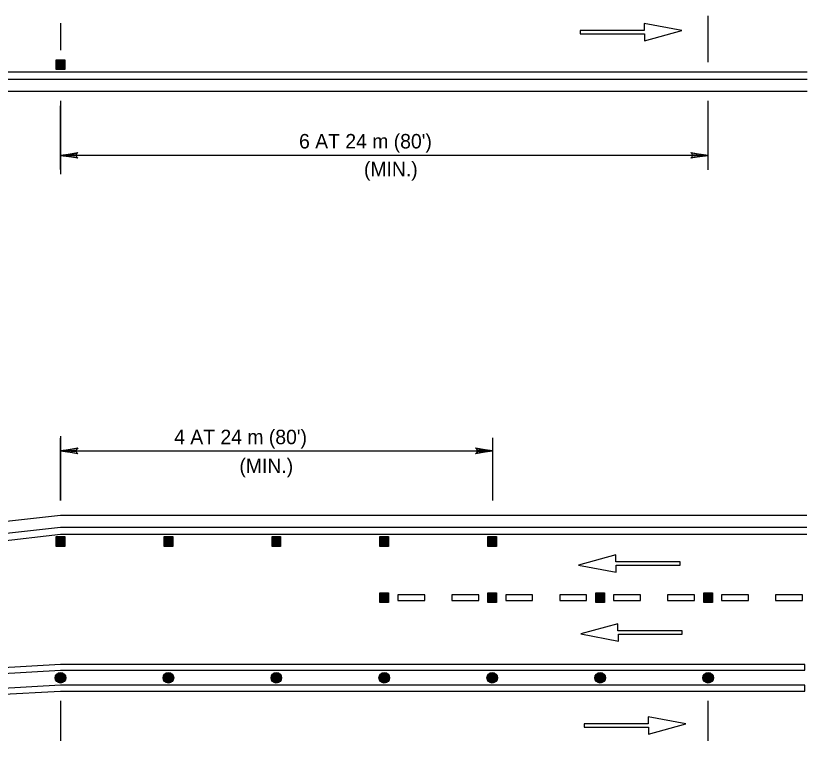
# Model space of a CAD drawing. Extents: x 639362 to 641108, y 298458 to 299646.
# Drawn here: x 639788.7 to 639952.7, y 298599.3 to 298751.3 of the extents above; entities that cross this region are included whole.
import ezdxf

# ---------------------------------------------------------------- set-up
doc = ezdxf.new("R2010")
doc.units = 0
doc.layers.add('2', color=7, linetype='Continuous')
doc.layers.add('3', color=7, linetype='Continuous')

# ---------------------------------------------------------------- blocks, each defined once
blk = doc.blocks.new('RARROW')
at = {"layer": '3'}
blk.add_lwpolyline([(-2.2695, 0.285), (-2.184875, 0.12075), (0, 0), (-2.2695, 0.285), (-2.38575, 0.384625), (0, 0), (-2.183125, -0.108), (-2.262875, -0.2705), (0, 0), (-2.38575, -0.379125), (-2.262875, -0.2705)], dxfattribs=at)

msp = doc.modelspace()

# ---------------------------------------------------------------- linework, layer by layer
at = {"layer": '2'}
for p, q in [((639932.2, 298741.66), (639932.2, 298751.3)), ((639798, 298749.76), (639798, 298744.18)), ((639926.74, 298748.22), (639918.93, 298749.7)), ((639918.93, 298749.7), (639918.93, 298748.25)), ((639918.93, 298748.25), (639905.69, 298748.25)), ((639905.69, 298748.25), (639905.69, 298747.55)), ((639905.69, 298747.55), (639919.02, 298747.55)), ((639919.02, 298746.1), (639926.74, 298748.22)), ((639919.02, 298747.55), (639919.02, 298746.1)), ((639797.11, 298740.14), (639797.11, 298742.18)), ((639797.11, 298742.18), (639798.88, 298742.18)), ((639797.28, 298740.32), (639797.28, 298742)), ((639797.28, 298742), (639798.7, 298742)), ((639797.46, 298740.5), (639797.46, 298741.83)), ((639797.46, 298741.83), (639798.53, 298741.83)), ((639797.64, 298740.67), (639797.64, 298741.65)), ((639797.64, 298741.65), (639798.35, 298741.65)), ((639797.82, 298740.85), (639797.82, 298741.47)), ((639797.82, 298741.47), (639798.17, 298741.47)), ((639798, 298741.03), (639798, 298741.29)), ((639798.17, 298741.47), (639798.17, 298740.85)), ((639798.35, 298741.65), (639798.35, 298740.67)), ((639798.53, 298741.83), (639798.53, 298740.5)), ((639798.7, 298742), (639798.7, 298740.32)), ((639798.88, 298742.18), (639798.88, 298740.14)), ((639431.35, 298739.66), (639952.74, 298739.66)), ((639798.88, 298740.14), (639797.11, 298740.14)), ((639798.7, 298740.32), (639797.28, 298740.32)), ((639798.53, 298740.5), (639797.46, 298740.5)), ((639798.35, 298740.67), (639797.64, 298740.67)), ((639798.17, 298740.85), (639797.82, 298740.85)), ((639431.35, 298738.16), (639952.74, 298738.16)), ((639431.35, 298735.66), (639952.74, 298735.66)), ((639798, 298733.66), (639798, 298718.46)), ((639932.2, 298719.36), (639932.2, 298733.66)), ((639798, 298719.43), (639798, 298732.66)), ((639932.2, 298722.36), (639798, 298722.36)), ((639797.99, 298664.16), (639797.99, 298650.81)), ((639798, 298650.81), (639798, 298663.74)), ((639887.61, 298650.81), (639887.61, 298663.83)), ((639798.01, 298661.11), (639887.61, 298661.11)), ((639585.9, 298624.2), (639797.99, 298647.81)), ((639797.99, 298647.81), (639951.12, 298647.81)), ((639797.99, 298647.81), (639952.64, 298647.81)), ((639585.9, 298621.7), (639797.99, 298645.31)), ((639797.99, 298645.31), (639951.12, 298645.31)), ((639797.99, 298645.31), (639952.64, 298645.31)), ((639585.9, 298620.2), (639797.99, 298643.81)), ((639797.11, 298641.29), (639797.11, 298643.33)), ((639797.11, 298643.33), (639798.88, 298643.33)), ((639797.28, 298641.47), (639797.28, 298643.16)), ((639797.28, 298643.16), (639798.7, 298643.16)), ((639797.46, 298641.65), (639797.46, 298642.98)), ((639797.46, 298642.98), (639798.53, 298642.98)), ((639797.64, 298641.83), (639797.64, 298642.8)), ((639797.64, 298642.8), (639798.35, 298642.8)), ((639797.82, 298642), (639797.82, 298642.62)), ((639797.82, 298642.62), (639798.17, 298642.62)), ((639797.99, 298643.81), (639951.12, 298643.81)), ((639797.99, 298643.81), (639952.64, 298643.81)), ((639798.17, 298642.62), (639798.17, 298642)), ((639798.35, 298642.8), (639798.35, 298641.83)), ((639798.53, 298642.98), (639798.53, 298641.65)), ((639798.7, 298643.16), (639798.7, 298641.47)), ((639798.88, 298643.33), (639798.88, 298641.29)), ((639819.47, 298641.29), (639819.47, 298643.33)), ((639819.47, 298643.33), (639821.25, 298643.33)), ((639819.65, 298641.47), (639819.65, 298643.16)), ((639819.65, 298643.16), (639821.07, 298643.16)), ((639819.83, 298641.65), (639819.83, 298642.98)), ((639819.83, 298642.98), (639820.89, 298642.98)), ((639820.01, 298641.83), (639820.01, 298642.8)), ((639820.01, 298642.8), (639820.72, 298642.8)), ((639820.18, 298642), (639820.18, 298642.62)), ((639820.18, 298642.62), (639820.54, 298642.62)), ((639820.54, 298642.62), (639820.54, 298642)), ((639820.72, 298642.8), (639820.72, 298641.83)), ((639820.89, 298642.98), (639820.89, 298641.65)), ((639821.07, 298643.16), (639821.07, 298641.47)), ((639821.25, 298643.33), (639821.25, 298641.29)), ((639841.84, 298641.29), (639841.84, 298643.33)), ((639841.84, 298643.33), (639843.62, 298643.33)), ((639842.02, 298641.47), (639842.02, 298643.16)), ((639842.02, 298643.16), (639843.44, 298643.16)), ((639842.2, 298641.65), (639842.2, 298642.98)), ((639842.2, 298642.98), (639843.26, 298642.98)), ((639842.37, 298641.83), (639842.37, 298642.8)), ((639842.37, 298642.8), (639843.08, 298642.8)), ((639842.55, 298642), (639842.55, 298642.62)), ((639842.55, 298642.62), (639842.91, 298642.62)), ((639842.91, 298642.62), (639842.91, 298642)), ((639843.08, 298642.8), (639843.08, 298641.83)), ((639843.26, 298642.98), (639843.26, 298641.65)), ((639843.44, 298643.16), (639843.44, 298641.47)), ((639843.62, 298643.33), (639843.62, 298641.29)), ((639864.21, 298641.29), (639864.21, 298643.33)), ((639864.21, 298643.33), (639865.98, 298643.33)), ((639864.39, 298641.47), (639864.39, 298643.16)), ((639864.39, 298643.16), (639865.81, 298643.16)), ((639864.56, 298641.65), (639864.56, 298642.98)), ((639864.56, 298642.98), (639865.63, 298642.98)), ((639864.74, 298641.83), (639864.74, 298642.8)), ((639864.74, 298642.8), (639865.45, 298642.8)), ((639864.92, 298642), (639864.92, 298642.62)), ((639864.92, 298642.62), (639865.27, 298642.62)), ((639865.27, 298642.62), (639865.27, 298642)), ((639865.45, 298642.8), (639865.45, 298641.83)), ((639865.63, 298642.98), (639865.63, 298641.65)), ((639865.81, 298643.16), (639865.81, 298641.47)), ((639865.98, 298643.33), (639865.98, 298641.29)), ((639886.58, 298641.29), (639886.58, 298643.33)), ((639886.58, 298643.33), (639888.35, 298643.33)), ((639886.75, 298641.47), (639886.75, 298643.16)), ((639886.75, 298643.16), (639888.17, 298643.16)), ((639886.93, 298641.65), (639886.93, 298642.98)), ((639886.93, 298642.98), (639888, 298642.98)), ((639887.11, 298641.83), (639887.11, 298642.8)), ((639887.11, 298642.8), (639887.82, 298642.8)), ((639887.29, 298642), (639887.29, 298642.62)), ((639887.29, 298642.62), (639887.64, 298642.62)), ((639887.64, 298642.62), (639887.64, 298642)), ((639887.82, 298642.8), (639887.82, 298641.83)), ((639888, 298642.98), (639888, 298641.65)), ((639888.17, 298643.16), (639888.17, 298641.47)), ((639888.35, 298643.33), (639888.35, 298641.29)), ((639798.88, 298641.29), (639797.11, 298641.29)), ((639798.7, 298641.47), (639797.28, 298641.47)), ((639798.53, 298641.65), (639797.46, 298641.65)), ((639798.35, 298641.83), (639797.64, 298641.83)), ((639798.17, 298642), (639797.82, 298642)), ((639798, 298642.18), (639798, 298642.45)), ((639821.25, 298641.29), (639819.47, 298641.29)), ((639821.07, 298641.47), (639819.65, 298641.47)), ((639820.89, 298641.65), (639819.83, 298641.65)), ((639820.72, 298641.83), (639820.01, 298641.83)), ((639820.54, 298642), (639820.18, 298642)), ((639820.36, 298642.18), (639820.36, 298642.45)), ((639843.62, 298641.29), (639841.84, 298641.29)), ((639843.44, 298641.47), (639842.02, 298641.47)), ((639843.26, 298641.65), (639842.2, 298641.65)), ((639843.08, 298641.83), (639842.37, 298641.83)), ((639842.91, 298642), (639842.55, 298642)), ((639842.73, 298642.18), (639842.73, 298642.45)), ((639865.98, 298641.29), (639864.21, 298641.29)), ((639865.81, 298641.47), (639864.39, 298641.47)), ((639865.63, 298641.65), (639864.56, 298641.65)), ((639865.45, 298641.83), (639864.74, 298641.83)), ((639865.27, 298642), (639864.92, 298642)), ((639865.1, 298642.18), (639865.1, 298642.45)), ((639888.35, 298641.29), (639886.58, 298641.29)), ((639888.17, 298641.47), (639886.75, 298641.47)), ((639888, 298641.65), (639886.93, 298641.65)), ((639887.82, 298641.83), (639887.11, 298641.83)), ((639887.64, 298642), (639887.29, 298642)), ((639887.47, 298642.18), (639887.47, 298642.45)), ((639913.08, 298639.53), (639905.36, 298637.42)), ((639913.08, 298638.09), (639913.08, 298639.53)), ((639926.41, 298638.09), (639913.08, 298638.09)), ((639926.41, 298637.39), (639926.41, 298638.09)), ((639905.36, 298637.42), (639913.16, 298635.94)), ((639913.16, 298635.94), (639913.16, 298637.39)), ((639913.16, 298637.39), (639926.41, 298637.39)), ((639864.21, 298629.65), (639864.21, 298631.69)), ((639864.21, 298631.69), (639865.98, 298631.69)), ((639864.39, 298629.83), (639864.39, 298631.51)), ((639864.39, 298631.51), (639865.81, 298631.51)), ((639864.56, 298630), (639864.56, 298631.33)), ((639864.56, 298631.33), (639865.63, 298631.33)), ((639864.74, 298630.18), (639864.74, 298631.15)), ((639864.74, 298631.15), (639865.45, 298631.15)), ((639865.45, 298631.15), (639865.45, 298630.18)), ((639865.63, 298631.33), (639865.63, 298630)), ((639865.81, 298631.51), (639865.81, 298629.83)), ((639865.98, 298631.69), (639865.98, 298629.65)), ((639873.49, 298631.27), (639867.89, 298631.27)), ((639867.89, 298631.27), (639867.89, 298630.07)), ((639873.49, 298630.07), (639873.49, 298631.27)), ((639884.67, 298631.27), (639879.08, 298631.27)), ((639879.08, 298631.27), (639879.08, 298630.07)), ((639884.67, 298630.07), (639884.67, 298631.27)), ((639886.58, 298629.65), (639886.58, 298631.69)), ((639886.58, 298631.69), (639888.35, 298631.69)), ((639886.75, 298629.83), (639886.75, 298631.51)), ((639886.75, 298631.51), (639888.17, 298631.51)), ((639886.93, 298630), (639886.93, 298631.33)), ((639886.93, 298631.33), (639888, 298631.33)), ((639887.11, 298630.18), (639887.11, 298631.15)), ((639887.11, 298631.15), (639887.82, 298631.15)), ((639887.82, 298631.15), (639887.82, 298630.18)), ((639888, 298631.33), (639888, 298630)), ((639888.17, 298631.51), (639888.17, 298629.83)), ((639888.35, 298631.69), (639888.35, 298629.65)), ((639895.85, 298631.27), (639890.26, 298631.27)), ((639890.26, 298631.27), (639890.26, 298630.07)), ((639895.85, 298630.07), (639895.85, 298631.27)), ((639907.04, 298631.27), (639901.45, 298631.27)), ((639901.45, 298631.27), (639901.45, 298630.07)), ((639907.04, 298630.07), (639907.04, 298631.27)), ((639908.94, 298629.65), (639908.94, 298631.69)), ((639908.94, 298631.69), (639910.72, 298631.69)), ((639909.12, 298629.83), (639909.12, 298631.51)), ((639909.12, 298631.51), (639910.54, 298631.51)), ((639909.3, 298630), (639909.3, 298631.33)), ((639909.3, 298631.33), (639910.36, 298631.33)), ((639909.48, 298630.18), (639909.48, 298631.15)), ((639909.48, 298631.15), (639910.19, 298631.15)), ((639910.19, 298631.15), (639910.19, 298630.18)), ((639910.36, 298631.33), (639910.36, 298630)), ((639910.54, 298631.51), (639910.54, 298629.83)), ((639910.72, 298631.69), (639910.72, 298629.65)), ((639918.22, 298631.27), (639912.63, 298631.27)), ((639912.63, 298631.27), (639912.63, 298630.07)), ((639918.22, 298630.07), (639918.22, 298631.27)), ((639929.41, 298631.27), (639923.81, 298631.27)), ((639923.81, 298631.27), (639923.81, 298630.07)), ((639929.41, 298630.07), (639929.41, 298631.27)), ((639931.31, 298629.65), (639931.31, 298631.69)), ((639931.31, 298631.69), (639933.09, 298631.69)), ((639931.49, 298629.83), (639931.49, 298631.51)), ((639931.49, 298631.51), (639932.91, 298631.51)), ((639931.67, 298630), (639931.67, 298631.33)), ((639931.67, 298631.33), (639932.73, 298631.33)), ((639931.84, 298630.18), (639931.84, 298631.15)), ((639931.84, 298631.15), (639932.55, 298631.15)), ((639932.55, 298631.15), (639932.55, 298630.18)), ((639932.73, 298631.33), (639932.73, 298630)), ((639932.91, 298631.51), (639932.91, 298629.83)), ((639933.09, 298631.69), (639933.09, 298629.65)), ((639940.59, 298631.27), (639935, 298631.27)), ((639935, 298631.27), (639935, 298630.07)), ((639940.59, 298630.07), (639940.59, 298631.27)), ((639951.77, 298631.27), (639946.18, 298631.27)), ((639946.18, 298631.27), (639946.18, 298630.07)), ((639951.77, 298630.07), (639951.77, 298631.27)), ((639865.98, 298629.65), (639864.21, 298629.65)), ((639865.81, 298629.83), (639864.39, 298629.83)), ((639865.63, 298630), (639864.56, 298630)), ((639865.45, 298630.18), (639864.74, 298630.18)), ((639864.92, 298630.35), (639864.92, 298630.98)), ((639864.92, 298630.98), (639865.27, 298630.98)), ((639865.27, 298630.35), (639864.92, 298630.35)), ((639865.1, 298630.53), (639865.1, 298630.8)), ((639865.27, 298630.98), (639865.27, 298630.35)), ((639867.89, 298630.07), (639873.49, 298630.07)), ((639879.08, 298630.07), (639884.67, 298630.07)), ((639888.35, 298629.65), (639886.58, 298629.65)), ((639888.17, 298629.83), (639886.75, 298629.83)), ((639888, 298630), (639886.93, 298630)), ((639887.82, 298630.18), (639887.11, 298630.18)), ((639887.29, 298630.35), (639887.29, 298630.98)), ((639887.29, 298630.98), (639887.64, 298630.98)), ((639887.64, 298630.35), (639887.29, 298630.35)), ((639887.47, 298630.53), (639887.47, 298630.8)), ((639887.64, 298630.98), (639887.64, 298630.35)), ((639890.26, 298630.07), (639895.85, 298630.07)), ((639901.45, 298630.07), (639907.04, 298630.07)), ((639910.72, 298629.65), (639908.94, 298629.65)), ((639910.54, 298629.83), (639909.12, 298629.83)), ((639910.36, 298630), (639909.3, 298630)), ((639910.19, 298630.18), (639909.48, 298630.18)), ((639909.65, 298630.35), (639909.65, 298630.98)), ((639909.65, 298630.98), (639910.01, 298630.98)), ((639910.01, 298630.35), (639909.65, 298630.35)), ((639909.83, 298630.53), (639909.83, 298630.8)), ((639910.01, 298630.98), (639910.01, 298630.35)), ((639912.63, 298630.07), (639918.22, 298630.07)), ((639923.81, 298630.07), (639929.41, 298630.07)), ((639933.09, 298629.65), (639931.31, 298629.65)), ((639932.91, 298629.83), (639931.49, 298629.83)), ((639932.73, 298630), (639931.67, 298630)), ((639932.55, 298630.18), (639931.84, 298630.18)), ((639932.02, 298630.35), (639932.02, 298630.98)), ((639932.02, 298630.98), (639932.38, 298630.98)), ((639932.38, 298630.35), (639932.02, 298630.35)), ((639932.2, 298630.53), (639932.2, 298630.8)), ((639932.38, 298630.98), (639932.38, 298630.35)), ((639935, 298630.07), (639940.59, 298630.07)), ((639946.18, 298630.07), (639951.77, 298630.07)), ((639913.53, 298625.26), (639905.81, 298623.15)), ((639913.53, 298623.82), (639913.53, 298625.26)), ((639905.81, 298623.15), (639913.61, 298621.67)), ((639926.86, 298623.82), (639913.53, 298623.82)), ((639913.61, 298621.67), (639913.61, 298623.11)), ((639913.61, 298623.11), (639926.86, 298623.11)), ((639926.86, 298623.11), (639926.86, 298623.82)), ((639797.98, 298616.83), (639585.9, 298604.78)), ((639952.26, 298616.83), (639797.98, 298616.83)), ((639798, 298616.83), (639797.99, 298616.83)), ((639952.26, 298615.63), (639952.26, 298616.83)), ((639585.93, 298603.58), (639798.02, 298615.63)), ((639798.02, 298615.63), (639952.26, 298615.63)), ((639797.98, 298612.52), (639585.9, 298600.47)), ((639952.26, 298612.52), (639797.98, 298612.52)), ((639952.26, 298611.32), (639952.26, 298612.52)), ((639585.93, 298599.27), (639798.02, 298611.32)), ((639798.02, 298611.32), (639952.26, 298611.32)), ((639798, 298609.32), (639798, 298601)), ((639932.2, 298601), (639932.2, 298609.32)), ((639927.57, 298604.51), (639919.76, 298605.99)), ((639919.76, 298605.99), (639919.76, 298604.55)), ((639919.76, 298604.55), (639906.52, 298604.55)), ((639906.52, 298604.55), (639906.52, 298603.84)), ((639906.52, 298603.84), (639919.84, 298603.84)), ((639919.84, 298602.4), (639927.57, 298604.51)), ((639919.84, 298603.84), (639919.84, 298602.4))]:
    msp.add_line(p, q, dxfattribs=at)
for centre, radius in [((639798.01, 298614.07), 1.1), ((639798.01, 298614.07), 1.02), ((639798.01, 298614.07), 0.946), ((639798.01, 298614.07), 0.868), ((639798.01, 298614.07), 0.789), ((639798.01, 298614.07), 0.711), ((639820.36, 298614.07), 1.1), ((639820.36, 298614.07), 1.02), ((639820.36, 298614.07), 0.946), ((639820.36, 298614.07), 0.868), ((639820.36, 298614.07), 0.789), ((639820.36, 298614.07), 0.711), ((639842.73, 298614.07), 1.1), ((639842.73, 298614.07), 1.02), ((639842.73, 298614.07), 0.946), ((639842.73, 298614.07), 0.868), ((639842.73, 298614.07), 0.789), ((639842.73, 298614.07), 0.711), ((639865.1, 298614.07), 1.1), ((639865.1, 298614.07), 1.02), ((639865.1, 298614.07), 0.946), ((639865.1, 298614.07), 0.868), ((639865.1, 298614.07), 0.789), ((639865.1, 298614.07), 0.711), ((639887.47, 298614.07), 1.1), ((639887.47, 298614.07), 1.02), ((639887.47, 298614.07), 0.946), ((639887.47, 298614.07), 0.868), ((639887.47, 298614.07), 0.789), ((639887.47, 298614.07), 0.711), ((639909.85, 298614.07), 1.1), ((639909.85, 298614.07), 1.02), ((639909.85, 298614.07), 0.946), ((639909.85, 298614.07), 0.868), ((639909.85, 298614.07), 0.789), ((639909.85, 298614.07), 0.711), ((639932.22, 298614.07), 1.1), ((639932.22, 298614.07), 1.02), ((639932.22, 298614.07), 0.946), ((639932.22, 298614.07), 0.868), ((639932.22, 298614.07), 0.789), ((639932.22, 298614.07), 0.711), ((639798.01, 298614.07), 0.633), ((639798.01, 298614.07), 0.554), ((639798.01, 298614.07), 0.476), ((639798.01, 298614.07), 0.398), ((639798.01, 298614.07), 0.32), ((639798.01, 298614.07), 0.241), ((639798.01, 298614.07), 0.163), ((639798.01, 298614.07), 0.0846), ((639820.36, 298614.07), 0.633), ((639820.36, 298614.07), 0.554), ((639820.36, 298614.07), 0.476), ((639820.36, 298614.07), 0.398), ((639820.36, 298614.07), 0.32), ((639820.36, 298614.07), 0.241), ((639820.36, 298614.07), 0.163), ((639820.36, 298614.07), 0.0846), ((639842.73, 298614.07), 0.633), ((639842.73, 298614.07), 0.554), ((639842.73, 298614.07), 0.476), ((639842.73, 298614.07), 0.398), ((639842.73, 298614.07), 0.32), ((639842.73, 298614.07), 0.241), ((639842.73, 298614.07), 0.163), ((639842.73, 298614.07), 0.0846), ((639865.1, 298614.07), 0.633), ((639865.1, 298614.07), 0.554), ((639865.1, 298614.07), 0.476), ((639865.1, 298614.07), 0.398), ((639865.1, 298614.07), 0.32), ((639865.1, 298614.07), 0.241), ((639865.1, 298614.07), 0.163), ((639865.1, 298614.07), 0.0846), ((639887.47, 298614.07), 0.633), ((639887.47, 298614.07), 0.554), ((639887.47, 298614.07), 0.476), ((639887.47, 298614.07), 0.398), ((639887.47, 298614.07), 0.32), ((639887.47, 298614.07), 0.241), ((639887.47, 298614.07), 0.163), ((639887.47, 298614.07), 0.0846), ((639909.85, 298614.07), 0.633), ((639909.85, 298614.07), 0.554), ((639909.85, 298614.07), 0.476), ((639909.85, 298614.07), 0.398), ((639909.85, 298614.07), 0.32), ((639909.85, 298614.07), 0.241), ((639909.85, 298614.07), 0.163), ((639909.85, 298614.07), 0.0846), ((639932.22, 298614.07), 0.633), ((639932.22, 298614.07), 0.554), ((639932.22, 298614.07), 0.476), ((639932.22, 298614.07), 0.398), ((639932.22, 298614.07), 0.32), ((639932.22, 298614.07), 0.241), ((639932.22, 298614.07), 0.163), ((639932.22, 298614.07), 0.0846)]:
    msp.add_circle(centre, radius, dxfattribs=at)

# ---------------------------------------------------------------- block references
at = {"layer": '2', "xscale": 1.5089217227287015, "yscale": 1.5711553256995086, "rotation": 180}
for p in [(639798, 298722.36), (639798.01, 298661.11)]:
    msp.add_blockref('RARROW', p, dxfattribs=at)
at = {"layer": '2', "xscale": 1.5089217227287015, "yscale": 1.5711553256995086}
for p in [(639932.2, 298722.36), (639887.61, 298661.11)]:
    msp.add_blockref('RARROW', p, dxfattribs=at)

# ---------------------------------------------------------------- texts
at = {"layer": '2'}
for s, p in [("6 AT 24 m (80')", (639847.44, 298723.8)), ('(MIN.)', (639860.89, 298718.03)), ("4 AT 24 m (80')", (639821.56, 298662.49)), ('(MIN.)', (639835.08, 298656.51))]:
    msp.add_text(s, height=3, dxfattribs=at).set_placement(p)

doc.saveas('drawing.dxf')
